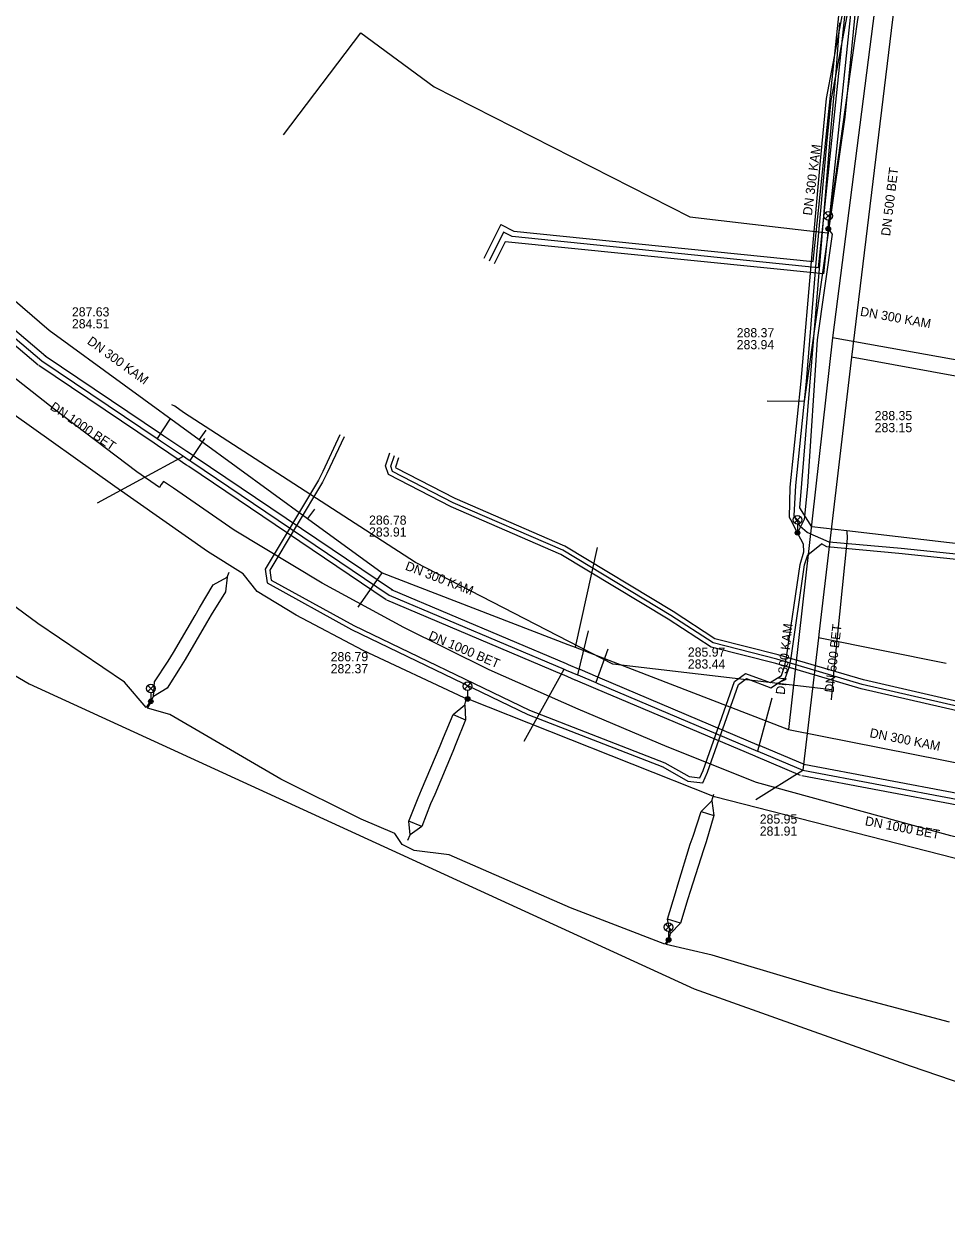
# Model space of a CAD drawing. Extents: x -595540 to -593988, y -1160850 to -1159202.
# Drawn here: x -594580.6 to -594500, y -1160463.7 to -1160358.3 of the extents above; entities that cross this region are included whole.
import ezdxf

# ---------------------------------------------------------------- set-up
doc = ezdxf.new("R2010")
doc.units = 0
for name, color, linetype in [('BVK-DESTOVA_popisy', 7, 'Continuous'), ('BVK-DESTOVA_trasa sítě', 7, 'Continuous'), ('BVK-DESTOVA_trasa sítě obvodem', 7, 'Continuous'), ('BVK-SPLASKOVA_popisy', 7, 'Continuous'), ('BVK-SPLASKOVA_trasa sítě', 7, 'Continuous'), ('BVK-VODOVOD_trasa sítě', 7, 'Continuous'), ('CETIN_kabel podzemní', 7, 'Continuous'), ('DESTOVA_trasa neprovozované sítě', 7, 'Continuous'), ('DPMB_trolejové vedení-nosné lano', 7, 'Continuous'), ('EON-NN_kabel', 7, 'Continuous'), ('EON-VN_kabel', 7, 'Continuous'), ('SPLASKOVA_neprovozovaná  trasa sítě', 7, 'Continuous'), ('TEPLARNY-HORKOVODY_trasa sítě', 7, 'Continuous'), ('TEPLARNY-HORKOVODY_trasa sítě obvodem', 7, 'Continuous'), ('TSB_kabel VO', 7, 'Continuous'), ('TSB_lampy VO', 7, 'Continuous')]:
    doc.layers.add(name, color=color, linetype=linetype)

msp = doc.modelspace()

# ---------------------------------------------------------------- linework, layer by layer
at = {"layer": 'BVK-DESTOVA_popisy'}
for p, q in [((-594506.348, -1160393.058), (-594506.348, -1160393.058)), ((-594553.855, -1160414.114), (-594553.855, -1160414.114)), ((-594516.384, -1160428.295), (-594516.384, -1160428.295))]:
    msp.add_line(p, q, dxfattribs=at)
at = {"layer": 'BVK-DESTOVA_trasa sítě'}
for p in [(-594504.651, -1160356.752), (-594488.218, -1160391.1)]:
    msp.add_line(p, (-594508.377, -1160387.435), dxfattribs=at)
for points in [[(-594608.872, -1160362.441), (-594600.737, -1160369.346), (-594600.342, -1160369.681), (-594598.259, -1160371.449), (-594598.229, -1160371.475), (-594597.925, -1160371.733), (-594579.063, -1160387.742)], [(-594579.063, -1160387.742), (-594568.991, -1160394.539), (-594568.701, -1160394.734), (-594566.704, -1160396.082), (-594566.297, -1160396.356), (-594566.165, -1160396.446), (-594565.974, -1160396.575), (-594548.741, -1160408.204)], [(-594508.377, -1160387.435), (-594511.199, -1160411.399), (-594511.263, -1160411.946), (-594512.625, -1160423.508)], [(-594548.741, -1160408.204), (-594533.452, -1160414.683), (-594533.277, -1160414.757), (-594532.311, -1160415.166), (-594532.274, -1160415.182), (-594530.708, -1160415.845), (-594530.515, -1160415.927), (-594516.593, -1160421.826), (-594516.547, -1160421.846), (-594512.625, -1160423.508)], [(-594512.625, -1160423.508), (-594499.055, -1160426.07), (-594498.799, -1160426.118), (-594485.622, -1160428.606), (-594485.111, -1160428.703), (-594483.775, -1160428.955), (-594483.547, -1160428.998)]]:
    msp.add_lwpolyline(points, dxfattribs=at)
at = {"layer": 'BVK-DESTOVA_trasa sítě obvodem'}
for points in [[(-594578.739, -1160387.361), (-594597.601, -1160371.351), (-594597.905, -1160371.093), (-594597.935, -1160371.068), (-594600.018, -1160369.3), (-594600.414, -1160368.964), (-594608.548, -1160362.06)], [(-594579.387, -1160388.123), (-594598.248, -1160372.114), (-594598.552, -1160371.856), (-594598.583, -1160371.83), (-594600.665, -1160370.063), (-594601.061, -1160369.727), (-594609.196, -1160362.822)], [(-594548.461, -1160407.79), (-594565.694, -1160396.16), (-594565.885, -1160396.032), (-594566.018, -1160395.942), (-594566.424, -1160395.668), (-594568.422, -1160394.32), (-594568.712, -1160394.124), (-594578.783, -1160387.328)], [(-594549.021, -1160408.618), (-594566.254, -1160396.989), (-594566.445, -1160396.86), (-594566.577, -1160396.771), (-594566.983, -1160396.497), (-594568.981, -1160395.149), (-594569.271, -1160394.953), (-594579.343, -1160388.156)], [(-594512.43, -1160423.048), (-594516.352, -1160421.386), (-594516.398, -1160421.366), (-594530.32, -1160415.467), (-594530.513, -1160415.385), (-594532.079, -1160414.722), (-594532.115, -1160414.706), (-594533.082, -1160414.296), (-594533.257, -1160414.222), (-594548.546, -1160407.744)], [(-594512.82, -1160423.968), (-594516.742, -1160422.306), (-594516.788, -1160422.287), (-594530.71, -1160416.388), (-594530.904, -1160416.306), (-594532.469, -1160415.642), (-594532.506, -1160415.627), (-594533.472, -1160415.217), (-594533.647, -1160415.143), (-594548.936, -1160408.664)], [(-594483.454, -1160428.507), (-594483.682, -1160428.464), (-594485.018, -1160428.211), (-594485.529, -1160428.115), (-594498.706, -1160425.627), (-594498.962, -1160425.579), (-594512.532, -1160423.017)], [(-594483.64, -1160429.489), (-594483.867, -1160429.446), (-594485.204, -1160429.194), (-594485.715, -1160429.098), (-594498.892, -1160426.61), (-594499.148, -1160426.561), (-594512.718, -1160423.999)]]:
    msp.add_lwpolyline(points, dxfattribs=at)
at = {"layer": 'BVK-SPLASKOVA_popisy'}
for p, q in [((-594576.449, -1160383.073), (-594576.449, -1160383.073)), ((-594518.395, -1160384.897), (-594518.395, -1160384.897)), ((-594550.501, -1160401.263), (-594550.501, -1160401.263)), ((-594522.664, -1160412.787), (-594522.664, -1160412.787))]:
    msp.add_line(p, q, dxfattribs=at)
at = {"layer": 'BVK-SPLASKOVA_trasa sítě'}
for p, q in [((-594506.046, -1160354.74), (-594510.032, -1160385.734)), ((-594510.032, -1160385.734), (-594513.871, -1160419.953)), ((-594489.609, -1160389.418), (-594510.032, -1160385.734)), ((-594513.871, -1160419.953), (-594467.309, -1160429.155))]:
    msp.add_line(p, q, dxfattribs=at)
for points in [[(-594607.618, -1160359.936), (-594600.103, -1160366.412), (-594578.449, -1160385.073)], [(-594578.449, -1160385.073), (-594565.346, -1160394.616), (-594565.225, -1160394.704), (-594555.864, -1160401.522), (-594549.344, -1160406.27)], [(-594549.344, -1160406.27), (-594533.138, -1160412.521), (-594532.512, -1160412.763), (-594513.871, -1160419.953)]]:
    msp.add_lwpolyline(points, dxfattribs=at)
at = {"layer": 'BVK-VODOVOD_trasa sítě'}
for p, q in [((-594567.459, -1160391.711), (-594567.72, -1160391.59)), ((-594508.771, -1160402.588), (-594508.753, -1160403.255)), ((-594508.753, -1160403.255), (-594510.079, -1160416.498)), ((-594510.1, -1160416.743), (-594510.13, -1160417.02)), ((-594510.079, -1160416.498), (-594510.1, -1160416.743)), ((-594510.13, -1160417.02), (-594510.161, -1160417.346))]:
    msp.add_line(p, q, dxfattribs=at)
for points in [[(-594508.771, -1160402.588), (-594511.83, -1160402.24), (-594512.89, -1160400.59), (-594510.23, -1160368.35), (-594509.72, -1160362.52), (-594509.39, -1160358.23)], [(-594510.079, -1160416.498), (-594529.212, -1160414.25), (-594546.444, -1160405.365), (-594566.697, -1160392.259), (-594567.459, -1160391.711)], [(-594414.938, -1160415.755), (-594416.18, -1160415.71), (-594419.89, -1160412.84), (-594422.8, -1160412.56), (-594448.8, -1160409.7), (-594488.88, -1160405.03), (-594495.32, -1160404.17), (-594508.771, -1160402.588)]]:
    msp.add_lwpolyline(points, dxfattribs=at)
at = {"layer": 'CETIN_kabel podzemní'}
for points in [[(-594677.72, -1160298.48), (-594662, -1160340.25), (-594667.08, -1160350.92), (-594656.1, -1160363.32), (-594647.95, -1160359.01), (-594597.96, -1160405.53), (-594580.17, -1160415.96), (-594522.1, -1160442.61), (-594503.24, -1160449.32), (-594487.31, -1160454.78), (-594463.83, -1160460.23), (-594443.09, -1160462.96), (-594437.19, -1160463.65)], [(-594507.43, -1160352.44), (-594507.63, -1160353.91), (-594508.01, -1160356.63), (-594508.96, -1160366.48), (-594510.4, -1160376.57)], [(-594557.98, -1160368), (-594551.22, -1160359.1), (-594544.81, -1160363.81), (-594522.49, -1160375.16), (-594514.29, -1160376.12), (-594511.02, -1160376.5), (-594510.4, -1160376.57)], [(-594510.4, -1160376.57), (-594512.5, -1160391.3), (-594515.73, -1160391.27)]]:
    msp.add_lwpolyline(points, dxfattribs=at)
at = {"layer": 'DESTOVA_trasa neprovozované sítě'}
for p, q in [((-594567.91, -1160392.834), (-594568.992, -1160394.539)), ((-594564.877, -1160394.532), (-594566.165, -1160396.446)), ((-594574.217, -1160400.159), (-594566.704, -1160396.082)), ((-594531.37, -1160411.339), (-594532.311, -1160415.166)), ((-594500.1, -1160414.17), (-594511.263, -1160411.946)), ((-594529.665, -1160412.942), (-594530.708, -1160415.845)), ((-594536.958, -1160420.981), (-594533.452, -1160414.683)), ((-594515.34, -1160417.21), (-594516.593, -1160421.826)), ((-594516.74, -1160426.06), (-594512.625, -1160423.508))]:
    msp.add_line(p, q, dxfattribs=at)
at = {"layer": 'DPMB_trolejové vedení-nosné lano'}
for points in [[(-594569.634, -1160417.651), (-594569.333, -1160417.08), (-594569.245, -1160415.78), (-594568.057, -1160413.982), (-594567.588, -1160413.232), (-594565.697, -1160409.992), (-594565.3, -1160409.311), (-594564.111, -1160407.308), (-594562.904, -1160406.638), (-594562.722, -1160406.22)], [(-594562.904, -1160406.638), (-594563.045, -1160407.925), (-594564.303, -1160409.93), (-594564.692, -1160410.638), (-594566.553, -1160413.824), (-594567.007, -1160414.543), (-594568.142, -1160416.346), (-594569.333, -1160417.08)], [(-594547.127, -1160429.613), (-594546.918, -1160429.153), (-594547.035, -1160427.95), (-594546.208, -1160425.913), (-594545.911, -1160425.21), (-594544.298, -1160421.368), (-594543.995, -1160420.649), (-594543.159, -1160418.629), (-594542.132, -1160417.803), (-594541.988, -1160417.208)], [(-594542.132, -1160417.803), (-594542.069, -1160419.118), (-594542.917, -1160421.192), (-594543.19, -1160421.872), (-594544.763, -1160425.612), (-594545.126, -1160426.441), (-594545.904, -1160428.422), (-594546.918, -1160429.153)], [(-594543.159, -1160418.629), (-594542.069, -1160419.118)], [(-594524.267, -1160438.207), (-594524.179, -1160437.779), (-594524.436, -1160436.507), (-594523.731, -1160434.21), (-594523.535, -1160433.513), (-594522.448, -1160429.956), (-594522.187, -1160429.25), (-594521.515, -1160427.105), (-594520.566, -1160426.179), (-594520.399, -1160425.588)], [(-594520.566, -1160426.179), (-594520.386, -1160427.456), (-594521.056, -1160429.768), (-594521.299, -1160430.451), (-594522.448, -1160434.091), (-594522.67, -1160434.725), (-594523.3, -1160436.856), (-594524.179, -1160437.779)], [(-594521.515, -1160427.105), (-594520.386, -1160427.456)], [(-594545.904, -1160428.422), (-594547.035, -1160427.95)], [(-594523.3, -1160436.856), (-594524.436, -1160436.507)]]:
    msp.add_lwpolyline(points, dxfattribs=at)
at = {"layer": 'EON-NN_kabel'}
for points in [[(-594494.128, -1160431.374), (-594494.422, -1160431.303), (-594494.239, -1160430.549), (-594499.689, -1160429.224), (-594516.668, -1160424.59), (-594524.466, -1160421.472), (-594532.254, -1160418.173), (-594540.017, -1160414.728), (-594547.466, -1160411.048), (-594554.592, -1160407.163), (-594562.286, -1160402.543), (-594567.568, -1160398.879), (-594568.466, -1160398.286), (-594568.653, -1160398.564), (-594568.813, -1160398.812), (-594570.774, -1160397.432), (-594578.002, -1160391.983), (-594584.064, -1160387.234)], [(-594499.148, -1160418.33), (-594507.543, -1160416.392), (-594514.995, -1160414.194), (-594520.618, -1160412.761), (-594524.377, -1160410.325), (-594533.764, -1160404.651), (-594543.337, -1160400.502), (-594548.793, -1160397.686), (-594549.055, -1160396.91), (-594548.692, -1160395.795)], [(-594499.071, -1160417.937), (-594507.441, -1160416.005), (-594514.889, -1160413.808), (-594520.456, -1160412.39), (-594524.165, -1160409.986), (-594533.58, -1160404.295), (-594543.166, -1160400.14), (-594548.466, -1160397.405), (-594548.615, -1160396.963), (-594548.271, -1160396.007)], [(-594498.994, -1160417.544), (-594507.339, -1160415.618), (-594514.783, -1160413.422), (-594520.294, -1160412.019), (-594523.953, -1160409.647), (-594533.396, -1160403.939), (-594542.995, -1160399.778), (-594548.139, -1160397.124), (-594548.175, -1160397.016), (-594547.895, -1160396.196)]]:
    msp.add_lwpolyline(points, dxfattribs=at)
at = {"layer": 'EON-VN_kabel'}
for points in [[(-594512.55, -1160404.43), (-594512.561, -1160403.767), (-594513.245, -1160402.502), (-594513.563, -1160401.844), (-594513.789, -1160401.425), (-594513.72, -1160398.775), (-594512.759, -1160389.517), (-594511.814, -1160378.396), (-594511.09, -1160370.284), (-594510.545, -1160364.848), (-594509.314, -1160358.256), (-594508.308, -1160352.93)], [(-594493.408, -1160401.037), (-594493.774, -1160403.505), (-594493.944, -1160404.397), (-594494.023, -1160404.739), (-594494.148, -1160404.82), (-594494.767, -1160404.983), (-594495.443, -1160404.99), (-594498.143, -1160404.744), (-594504.051, -1160404.136), (-594510.328, -1160403.578), (-594512.254, -1160402.746), (-594512.85, -1160402.223), (-594513.095, -1160401.769), (-594513.368, -1160401.285), (-594513.229, -1160398.643), (-594512.315, -1160389.542), (-594511.399, -1160378.471), (-594510.528, -1160368.834), (-594510.142, -1160365.02), (-594508.851, -1160358.091), (-594507.908, -1160352.983)], [(-594553.051, -1160394.206), (-594554.54, -1160397.412), (-594554.925, -1160398.163), (-594559.589, -1160405.949), (-594559.403, -1160407.148), (-594552.022, -1160411.218), (-594536.64, -1160418.624), (-594524.836, -1160423.211), (-594522.663, -1160424.454), (-594521.355, -1160424.595), (-594520.954, -1160423.663), (-594518.242, -1160416.013), (-594517.557, -1160415.496), (-594515.415, -1160416.303), (-594514.164, -1160415.48), (-594513.796, -1160414.452), (-594513.653, -1160413.683), (-594512.472, -1160405.575), (-594512.175, -1160404.686), (-594510.99, -1160403.74)], [(-594552.689, -1160394.374), (-594554.18, -1160397.588), (-594554.575, -1160398.357), (-594559.171, -1160406.031), (-594559.037, -1160406.892), (-594551.838, -1160410.862), (-594536.48, -1160418.256), (-594524.664, -1160422.849), (-594522.537, -1160424.066), (-594521.605, -1160424.165), (-594521.326, -1160423.517), (-594518.578, -1160415.767), (-594517.623, -1160415.044), (-594515.465, -1160415.857), (-594514.496, -1160415.22), (-594514.184, -1160414.348), (-594514.047, -1160413.617), (-594512.868, -1160405.525), (-594512.55, -1160404.43)], [(-594492.175, -1160401.095), (-594492.656, -1160403.76), (-594493.05, -1160404.563), (-594493.462, -1160404.951), (-594494.164, -1160405.357), (-594495.038, -1160405.477), (-594498.379, -1160405.186), (-594504.24, -1160404.567), (-594510.529, -1160404.007), (-594510.99, -1160403.74)]]:
    msp.add_lwpolyline(points, dxfattribs=at)
at = {"layer": 'SPLASKOVA_neprovozovaná  trasa sítě'}
for p, q in [((-594564.757, -1160393.808), (-594565.346, -1160394.616)), ((-594555.275, -1160400.713), (-594555.864, -1160401.522)), ((-594530.581, -1160404.064), (-594532.512, -1160412.763)), ((-594551.45, -1160409.27), (-594549.344, -1160406.27))]:
    msp.add_line(p, q, dxfattribs=at)
at = {"layer": 'TEPLARNY-HORKOVODY_trasa sítě'}
msp.add_line((-594538.776, -1160376.524), (-594540.025, -1160379.043), dxfattribs=at)
msp.add_lwpolyline([(-594508.356, -1160351.505), (-594511.277, -1160379.614), (-594538.013, -1160376.903), (-594538.776, -1160376.524)], dxfattribs=at)
at = {"layer": 'TEPLARNY-HORKOVODY_trasa sítě obvodem'}
for p, q in [((-594539.002, -1160375.853), (-594540.473, -1160378.821)), ((-594538.624, -1160377.344), (-594539.577, -1160379.265))]:
    msp.add_line(p, q, dxfattribs=at)
for points in [[(-594539.002, -1160375.853), (-594537.872, -1160376.415), (-594511.723, -1160379.066), (-594508.853, -1160351.453)], [(-594507.858, -1160351.557), (-594510.831, -1160380.161), (-594538.624, -1160377.344)]]:
    msp.add_lwpolyline(points, dxfattribs=at)
at = {"layer": 'TSB_kabel VO'}
for points in [[(-594505.239, -1160320.305), (-594504.78, -1160320.38), (-594503.646, -1160321.344), (-594503.85, -1160324.431), (-594504.226, -1160327.223), (-594504.82, -1160327.124), (-594504.226, -1160327.223), (-594505.52, -1160332.203), (-594506.719, -1160342.814), (-594507.698, -1160351.064), (-594507.363, -1160352.504), (-594507.415, -1160355.214), (-594507.873, -1160358.156), (-594510.406, -1160376.216), (-594510.075, -1160376.681), (-594511.372, -1160385.904), (-594512.208, -1160398.733), (-594512.511, -1160401.619), (-594513.094, -1160402.772)], [(-594541.899, -1160417.28), (-594542.2, -1160417.19), (-594551.03, -1160413.04), (-594556.87, -1160409.95), (-594560.28, -1160407.89), (-594561.49, -1160406.35), (-594564.6, -1160404.41), (-594572.71, -1160398.73), (-594581.689, -1160392.317)], [(-594499.82, -1160445.5), (-594510.12, -1160442.77), (-594520.55, -1160439.67), (-594524.567, -1160438.735), (-594524.376, -1160438.469), (-594524.348, -1160438.328), (-594524.473, -1160438.399), (-594524.688, -1160438.698), (-594532.91, -1160435.52), (-594543.51, -1160430.88), (-594546.57, -1160430.51), (-594547.62, -1160430), (-594548.25, -1160429.04), (-594551.2, -1160427.78), (-594558.21, -1160424.28), (-594567.9, -1160418.63), (-594569.86, -1160418.077), (-594569.582, -1160417.642), (-594569.557, -1160417.491), (-594569.683, -1160417.577), (-594569.961, -1160418.013), (-594571.86, -1160415.82), (-594579.44, -1160410.68), (-594588.24, -1160404.19)], [(-594496.91, -1160431.839), (-594520.335, -1160425.841), (-594541.899, -1160417.28)]]:
    msp.add_lwpolyline(points, dxfattribs=at)
at = {"layer": 'TSB_lampy VO'}
for p, q in [((-594510.671, -1160375.356), (-594510.141, -1160374.826)), ((-594510.671, -1160374.826), (-594510.141, -1160375.356)), ((-594510.671, -1160375.356), (-594510.141, -1160374.826)), ((-594510.671, -1160374.826), (-594510.141, -1160375.356)), ((-594510.406, -1160375.466), (-594510.406, -1160376.216)), ((-594510.406, -1160375.466), (-594510.406, -1160376.216)), ((-594513.359, -1160401.912), (-594512.829, -1160401.382)), ((-594513.359, -1160401.382), (-594512.829, -1160401.912)), ((-594513.359, -1160401.912), (-594512.829, -1160401.382)), ((-594513.359, -1160401.382), (-594512.829, -1160401.912)), ((-594513.094, -1160402.022), (-594513.094, -1160402.772)), ((-594513.094, -1160402.022), (-594513.094, -1160402.772)), ((-594569.822, -1160416.631), (-594569.292, -1160416.101)), ((-594569.822, -1160416.101), (-594569.292, -1160416.631)), ((-594569.822, -1160416.631), (-594569.292, -1160416.101)), ((-594569.822, -1160416.101), (-594569.292, -1160416.631)), ((-594569.557, -1160416.741), (-594569.557, -1160417.491)), ((-594569.557, -1160416.741), (-594569.557, -1160417.491)), ((-594542.164, -1160416.42), (-594541.634, -1160415.89)), ((-594542.164, -1160415.89), (-594541.634, -1160416.42)), ((-594542.164, -1160416.42), (-594541.634, -1160415.89)), ((-594542.164, -1160415.89), (-594541.634, -1160416.42)), ((-594541.899, -1160416.53), (-594541.899, -1160417.28)), ((-594541.899, -1160416.53), (-594541.899, -1160417.28)), ((-594524.613, -1160437.468), (-594524.083, -1160436.938)), ((-594524.613, -1160436.938), (-594524.083, -1160437.468)), ((-594524.613, -1160437.468), (-594524.083, -1160436.938)), ((-594524.613, -1160436.938), (-594524.083, -1160437.468)), ((-594524.348, -1160437.578), (-594524.348, -1160438.328)), ((-594524.348, -1160437.578), (-594524.348, -1160438.328))]:
    msp.add_line(p, q, dxfattribs=at)
for centre, radius in [((-594510.406, -1160375.091), 0.375), ((-594510.406, -1160375.091), 0.375), ((-594510.406, -1160376.216), 0.2), ((-594510.406, -1160376.216), 0.2), ((-594510.406, -1160376.216), 0.145), ((-594510.406, -1160376.216), 0.145), ((-594510.406, -1160376.216), 0.0876), ((-594510.406, -1160376.216), 0.0876), ((-594513.094, -1160401.647), 0.375), ((-594513.094, -1160401.647), 0.375), ((-594513.094, -1160402.772), 0.2), ((-594513.094, -1160402.772), 0.2), ((-594513.094, -1160402.772), 0.145), ((-594513.094, -1160402.772), 0.145), ((-594513.094, -1160402.772), 0.0876), ((-594513.094, -1160402.772), 0.0876), ((-594541.899, -1160416.155), 0.375), ((-594541.899, -1160416.155), 0.375), ((-594569.557, -1160416.366), 0.375), ((-594569.557, -1160416.366), 0.375), ((-594569.557, -1160417.491), 0.2), ((-594569.557, -1160417.491), 0.2), ((-594569.557, -1160417.491), 0.145), ((-594569.557, -1160417.491), 0.145), ((-594569.557, -1160417.491), 0.0876), ((-594569.557, -1160417.491), 0.0876), ((-594541.899, -1160417.28), 0.2), ((-594541.899, -1160417.28), 0.2), ((-594541.899, -1160417.28), 0.145), ((-594541.899, -1160417.28), 0.145), ((-594541.899, -1160417.28), 0.0876), ((-594541.899, -1160417.28), 0.0876), ((-594524.348, -1160437.203), 0.375), ((-594524.348, -1160437.203), 0.375), ((-594524.348, -1160438.328), 0.2), ((-594524.348, -1160438.328), 0.2), ((-594524.348, -1160438.328), 0.145), ((-594524.348, -1160438.328), 0.145), ((-594524.348, -1160438.328), 0.0876), ((-594524.348, -1160438.328), 0.0876)]:
    msp.add_circle(centre, radius, dxfattribs=at)

# ---------------------------------------------------------------- texts
at = {"layer": 'BVK-DESTOVA_popisy'}
for s, rotation, p in [('DN 500 BET', 83.07888, (-594505.007, -1160376.883)), ('DN 1000 BET', 326.01299, (-594578.428, -1160391.941)), ('DN 1000 BET', 337.01377, (-594545.374, -1160412.033)), ('DN 500 BET', 83.30806, (-594509.936, -1160416.763)), ('DN 1000 BET', 349.33238, (-594507.24, -1160428.3))]:
    msp.add_text(s, height=0.8, rotation=rotation, dxfattribs=at).set_placement(p)
for s, p in [('288.35', (-594506.348, -1160392.933)), ('283.15', (-594506.348, -1160393.983)), ('286.79', (-594553.855, -1160413.989)), ('282.37', (-594553.855, -1160415.039)), ('285.95', (-594516.384, -1160428.17)), ('281.91', (-594516.384, -1160429.22))]:
    msp.add_text(s, height=0.8, dxfattribs=at).set_placement(p)
at = {"layer": 'BVK-SPLASKOVA_popisy'}
for rotation, p in [(82.67781, (-594511.837, -1160375.09)), (349.75339, (-594507.661, -1160383.803)), (323.95033, (-594575.181, -1160386.201)), (338.90453, (-594547.405, -1160405.977)), (83.59454, (-594514.207, -1160416.938)), (348.81671, (-594506.834, -1160420.607))]:
    msp.add_text('DN 300 KAM', height=0.8, rotation=rotation, dxfattribs=at).set_placement(p)
for s, p in [('287.63', (-594576.449, -1160383.873)), ('284.51', (-594576.449, -1160384.913)), ('288.37', (-594518.395, -1160385.697)), ('283.94', (-594518.395, -1160386.737)), ('286.78', (-594550.501, -1160402.063)), ('283.91', (-594550.501, -1160403.103)), ('285.97', (-594522.664, -1160413.587)), ('283.44', (-594522.664, -1160414.627))]:
    msp.add_text(s, height=0.8, dxfattribs=at).set_placement(p)

doc.saveas('drawing.dxf')
